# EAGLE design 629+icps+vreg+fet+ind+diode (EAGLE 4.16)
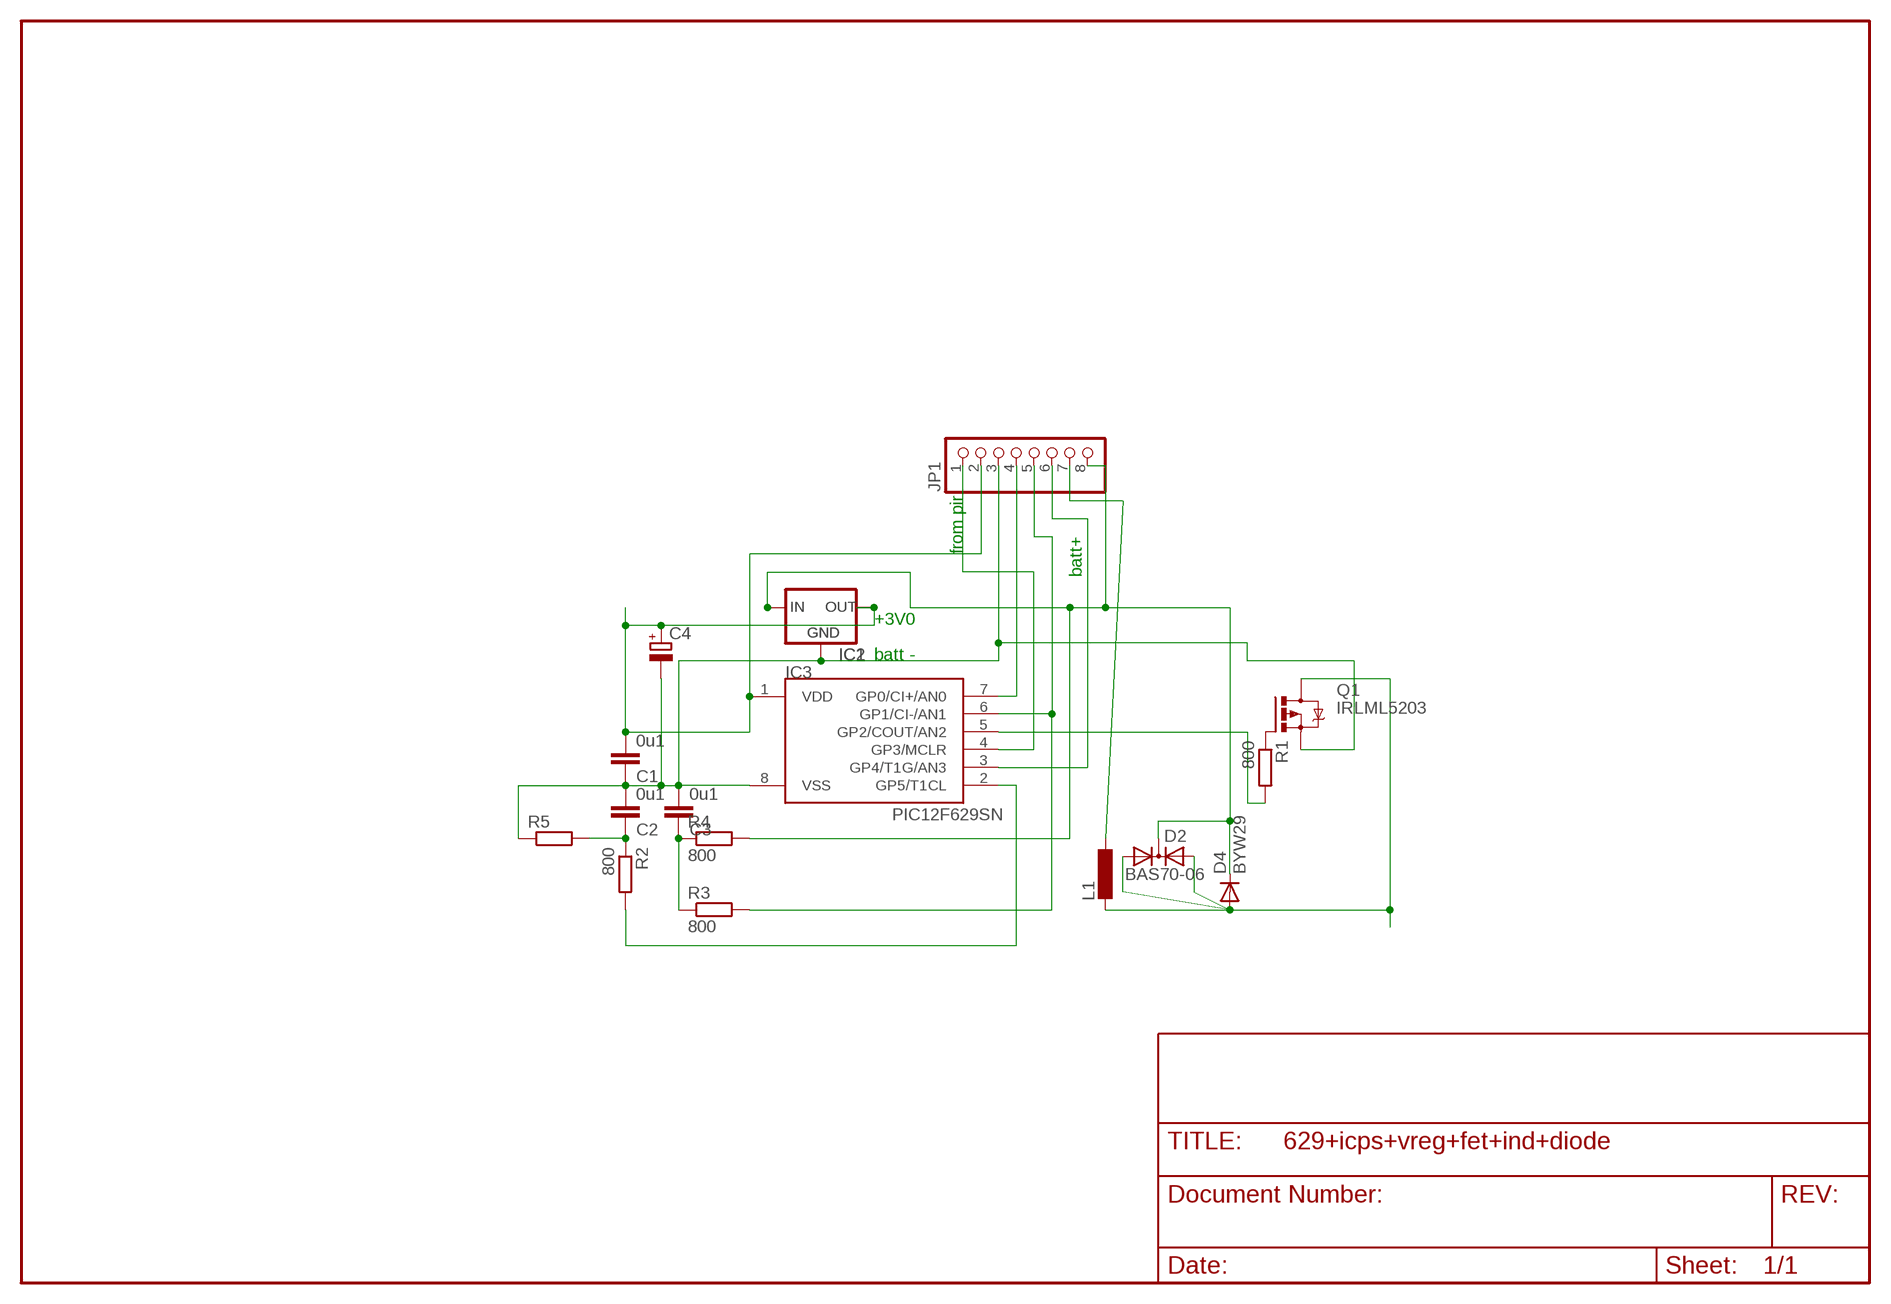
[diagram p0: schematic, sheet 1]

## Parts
C1  0u1  C-EUC1206  [C1206]
C2  0u1  C-EUC1206  [C1206]
C3  0u1  C-EUC1206  [C1206]
C4  CPOL-EUE2.5-6  [E2,5-6]
D2  BAS70-06  [SOT23]
D4  BYW29  [DO220S]
IC1  XC63FPP  [SOT89R]
IC2  XC63FPT  [TO92]
IC3  PIC12F629SN  [SO-08]
JP1  PINHD-1X8  [1X08]
L1  L-EU0207/7  [0207/7]
Q1  IRLML5203  [MICRO3]
R1  800  R-EU_R1206  [R1206]
R2  800  R-EU_R1206  [R1206]
R3  800  R-EU_R1206  [R1206]
R4  800  R-EU_R1206  [R1206]
R5  R-EU_0411/3V  [0411V]

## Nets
N$1: C1.1 C2.2 C3.2 C4.- IC1.1(GND) IC2.1(GND) IC3.8(VSS) JP1.3 Q1.2(S) R5.1
N$2: IC3.2(GP5/T1CL) R2.2
N$3: D2.3(C) D4.C IC1.2(IN) IC2.2(IN) JP1.8 R4.2
N$4: IC3.6(GP1/CI-/AN1) JP1.5 R3.2
N$5: D2.1(A1) D2.2(A2) D4.A L1.2 Q1.3(D)
N$6: C1.2 C4.+ IC1.3(OUT) IC2.3(OUT) IC3.1(VDD) JP1.2
N$7: C3.1 R3.1 R4.1
N$8: JP1.7 L1.1
N$9: IC3.4(GP3/MCLR) JP1.1
N$11: C2.1 R2.1 R5.2
N$12: Q1.1(G) R1.1
N$14: IC3.7(GP0/CI+/AN0) JP1.4
N$16: IC3.5(GP2/COUT/AN2) R1.2
N$17: IC3.3(GP4/T1G/AN3) JP1.6

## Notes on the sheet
- batt+
- from pir
- +3V0
- batt -

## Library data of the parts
C1-C3 = rcl:C-EU: CAPACITOR, European symbol
C4 = rcl(2):CPOL-EU: POLARIZED CAPACITOR, European symbol
D2 = diode-1:BAS70-06: Silicon Schottky Diodes General-purpose diode for high-speed switching
D4 = diode:BYW29: DIODE
IC1 IC2 = v-reg:XC63FP: Positiv Voltage Regulators www.torex.co.jp/english/product/pro02/pdf/0201_xc62fp.pdf
IC3 = microchip-3:PIC12F6*: uPC nW 1k Program Flash memory 2x Timer Comparator 10b A/D converter/ 4xIN
JP1 = pinhead(2):PINHD-1X8: PIN HEADER
L1 = rcl:L-EU: INDUCTOR, European symbol
Q1 = transistor-power:IRLML5203: HEXFET P-Channel Power MOSFET
R1-R5 = rcl:R-EU_: RESISTOR, European symbol

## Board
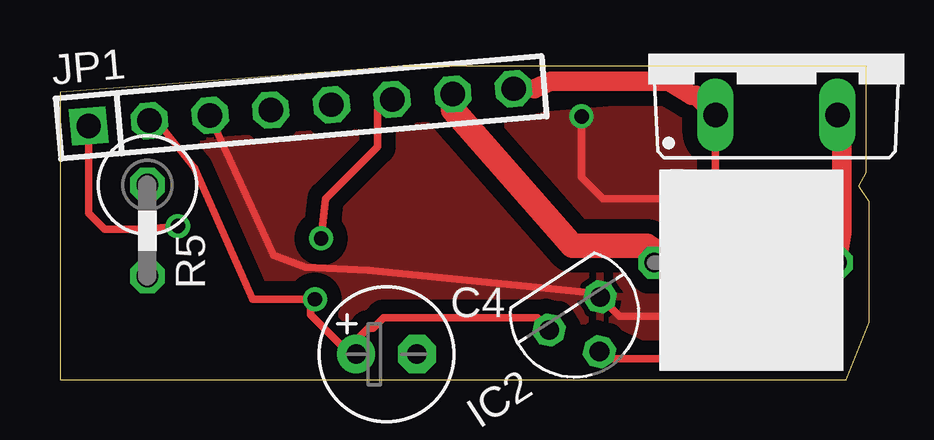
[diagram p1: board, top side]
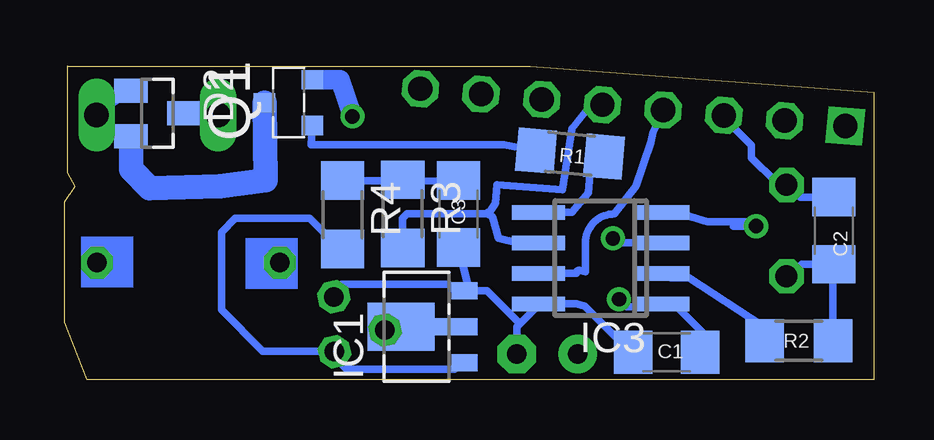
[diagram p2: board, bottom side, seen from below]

Size 33.74 x 13.08 mm. Coordinates in mm from the lower left corner, seen from the top.
Outline: 33.62,13.07 33.62,8.63 33.3,8.06 33.74,7.42 33.74,2.41 32.79,0 0,0 0,11.99 14.31,13.08 18,13.07 33.62,13.07
Outline: 33.62,13.07 33.64,13.07
Copper layers (1*16): Top 0.035mm / dielectric 1.5mm / Bottom 0.035mm
Design rules "default": minimum track width 10mil, minimum drill 24mil, track to track 8mil, track to pad 8mil, pad to pad 8mil, via to via 8mil, smd to smd 8mil, copper to edge 1mil, drill to drill 8mil, minimum pad ring 10mil, minimum via ring 8mil, stop-mask expansion 4mil, vias tented up to drill 0mil, thermal gap 10mil

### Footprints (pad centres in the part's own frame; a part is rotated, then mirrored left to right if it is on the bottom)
C1206 = smd 1.6 x 1.8: 1 -1.4,0; 2 1.4,0
E2,5-6 = drill 0.813 pad 1.6 round: + -1.27,0 | drill 0.813 pad 1.6 octagon: - 1.27,0
SOT23 = smd 1 x 1.4: 1 -0.95,-1.1; 2 0.95,-1.1; 3 0,1.1
DO220S = drill 1.016 long: A 2.54,-2.54; C -2.54,-2.54
SOT89R = smd 0.7 x 1.1: 1 1.5,-1.75; 2 -1.5,-1.75 | smd 0.7 x 1.8: 3 0,-1.4 | smd 2 x 2.8: 4 0,0.9
TO92 = drill 0.813 octagon: 1 -1.27,0; 2 0,1.905; 3 1.27,0
SO-08 = smd 0.6 x 2.2: 1 -1.905,-2.6; 2 -0.635,-2.6; 3 0.635,-2.6; 4 1.905,-2.6; 5 1.905,2.6; 6 0.635,2.6; 7 -0.635,2.6; 8 -1.905,2.6
1X08 = drill 1.016 square: 1 -8.89,0 | drill 1.016 octagon: 2 -6.35,0; 3 -3.81,0; 4 -1.27,0; 5 1.27,0; 6 3.81,0; 7 6.35,0; 8 8.89,0
0207/7 = drill 0.813 octagon: 1 -3.81,0; 2 3.81,0
MICRO3 = smd 0.8 x 0.9: 1 -0.95,-1; 2 0.95,-1; 3 0,1
R1206 = smd 1.6 x 1.803: 1 -1.422,0; 2 1.422,0
0411V = drill 0.914 octagon: 1 -2.54,0; 2 1.27,0

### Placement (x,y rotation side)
C1  8.64,1.15 0 bottom
C2  1.68,6.22 90 bottom
C3  17.32,6.92 270 bottom
C4  13.61,1.07 0 top
D2  29.87,11.11 270 bottom
D4  29.87,13.58 0 top
IC1  18.82,2.22 90 bottom
IC2  21.45,2.77 213 top
IC3  11.39,5.08 90 bottom
JP1  10.05,11.36 5 top
L1  28.58,4.88 0 top
Q1  24.41,11.55 90 bottom
R1  12.67,9.43 355 bottom
R2  3.13,1.63 180 bottom
R3  19.65,6.92 270 bottom
R4  22.15,6.88 270 bottom
R5  3.65,5.58 270 top

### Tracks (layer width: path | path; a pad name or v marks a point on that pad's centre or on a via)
N$1  (via drill 0.6)
  Top 0.305: v21.74,10.98 21.74,8.44 22.63,7.55 25.68,7.55 25.74,7.62 27.71,5.65 27.71,4.82 25.55,2.66 23.33,2.66 22.53,3.46 IC2.1 | JP1.3 6.26,10.97 8.92,5.2 10.25,4.69 12.85,4.57 22.31,3.61 | 22.52,3.41 22.69,3.23 | 22.52,3.41 IC2.1 | 22.31,3.61 22.52,3.41 | 22.31,3.61 22.12,3.81 | 22.31,3.61 IC2.1
  Bottom 0.305: IC1.1 17.46,3.72 17.74,4 22.19,4 22.69,3.49 22.67,3.46 IC2.1 | C4.- 14.88,2.22 14.76,2.34 | 14.76,2.34 13.99,3.11 IC3.8 12.41,3.17 12.06,3.07 10.07,1.09 C1.1 | 3.64,8.19 3.71,8.25 4.09,8.25 5.11,9.27 5.11,9.77 6.36,11.02 | 3.64,8.19 R5.1 | C2.2 3.08,7.62 3.64,8.19 | IC1.1 17.07,3.64 17.04,3.61 16.88,3.78 C3.2 | IC1.1 16.13,3.72 14.76,2.34 | 6.36,11.02 6.38,11.04 | 6.36,11.02 JP1.3
  Bottom 0.813: Q1.2 22.25,12.5 v21.74,10.98
  pour Top (isolate 0.61): 4.6,9.84 7.33,3.36 11.01,3.36 11.58,2.54 23.2,2.34 24.47,1.71 29.11,2.03 28.98,5.9 25.68,11.49 16.6,10.73 14.44,10.54
N$2
  Bottom 0.305: R2.2 4.64,2.26 7.71,4.25 8.47,4.25 8.73,4.5 IC3.2
N$3
  Top 0.305: D4.C 27.33,8.12 29.43,6.03 29.43,1.96 29.49,1.9 27.01,1.9 26,0.88 22.89,0.88 22.5,1.27 22.49,1.25 IC2.2 | 19.78,12.13 JP1.8 | 26.51,11.87 26.31,11.87
  Top 0.813: 19.78,12.13 20.47,12.44 25.36,12.44 26.31,11.87 | D4.C 26.51,11.87
  Bottom 0.305: IC1.2 17.21,0.72 17.49,0.44 22,0.44 22.49,0.93 IC2.2 22.49,1.09 22.5,1.07 22.63,1.2 25.49,1.2 27.2,2.92 27.2,6.16 26.63,6.73 23.52,6.73 22.25,5.46 R4.2 | D2.3 28.66,11.11 28.54,10.98 27.39,10.98 D4.C
N$4
  Bottom 0.305: IC3.6 14.88,5.71 15.65,5.9 15.9,6.79 16.15,6.92 | 16.15,6.92 16.09,6.92 16.09,6.98 16.03,6.98 15.77,7.36 15.71,8.12 12.98,7.93 12.6,10.47 11.8,11.47 JP1.5 | 16.15,6.92 19.46,6.92 19.65,6.73 R3.2
N$5
  Top 0.305: D4.A 32.47,10.92 32.6,10.15
  Top 0.813: L1.2 32.6,6.16 32.6,10.15
  Bottom 0.305: D2.2 31.46,10.16 32.35,11.04 D4.A 32.28,11.17 D2.1
  Bottom 1.016: D2.2 30.97,8.78 30.19,8 27.27,8.06 25.36,8.31 Q1.3
N$6  (via drill 0.6)
  Top 0.305: 4.2,10.8 JP1.2 4.03,10.79 5.61,8.82 8.03,3.36 v10.63,3.36 10.44,3.17 10.44,2.73 12.09,1.07 C4.+ 12.34,1.65 12.85,2.15 13.04,2.15 13.49,2.6 19.9,2.6 20.42,2.08 | 20.42,2.08 20.54,1.96 | 20.42,2.08 IC2.3
  Bottom 0.305: IC3.1 9.04,3.17 | v10.63,3.36 10.31,3.04 8.92,3.04 IC3.1 | IC3.1 8.22,3.04 6.74,1.56 C1.2 | IC2.3 20.4,2.08 20.41,2.09 20.28,2.22 IC1.3
N$7
  Bottom 0.305: 19.67,8.34 19.71,8.38 | 19.67,8.34 R3.1 19.74,8.34 19.77,8.38 19.85,8.3 R4.1 | C3.1 19.59,8.25 19.67,8.34
N$8
  Top 1.016: JP1.7 16.38,11.26 21.36,5.58 24.47,5.58 24.66,5.46 24.66,5.14 24.92,4.88 L1.1
N$9  (via drill 0.6)
  Top 0.305: JP1.1 1.2,6.95 1.87,6.28 3.45,6.28 v4.91,6.41
  Bottom 0.305: v4.91,6.41 5.87,6.41 4.72,6.6 6.95,6.6 7.84,6.85 8.66,6.85 IC3.4
N$11
  Bottom 0.305: C2.1 1.61,4.88 | C2.1 3.01,4.82 3.52,4.31 R5.2 | R2.1 1.71,4.79 C2.1
N$12
  Bottom 0.305: Q1.1 23.47,9.79 15.42,9.8 R1.1
N$14
  Bottom 0.305: IC3.7 12.41,4.44 arc90 12.28,4.57 12.03,4.5 12.03,5.71 arc90 10.82,6.92 9.93,8.06 9.3,9.9 9.22,10.29 JP1.4
N$16
  Bottom 0.305: R1.2 11.89,8.64 11.07,8.69 11.84,8.57 11.9,7.81 12.6,6.98 IC3.5
N$17  (via drill 0.6)
  Top 0.305: v10.88,5.9 11.07,7.55 13.23,9.71 13.23,11.23 13.85,11.85 | 13.85,11.85 13.93,11.93 | 13.85,11.85 JP1.6
  Bottom 0.305: IC3.3 10.63,5.71 v10.88,5.9
(copper drawn outside any net)
  shapes: Bottom area x2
